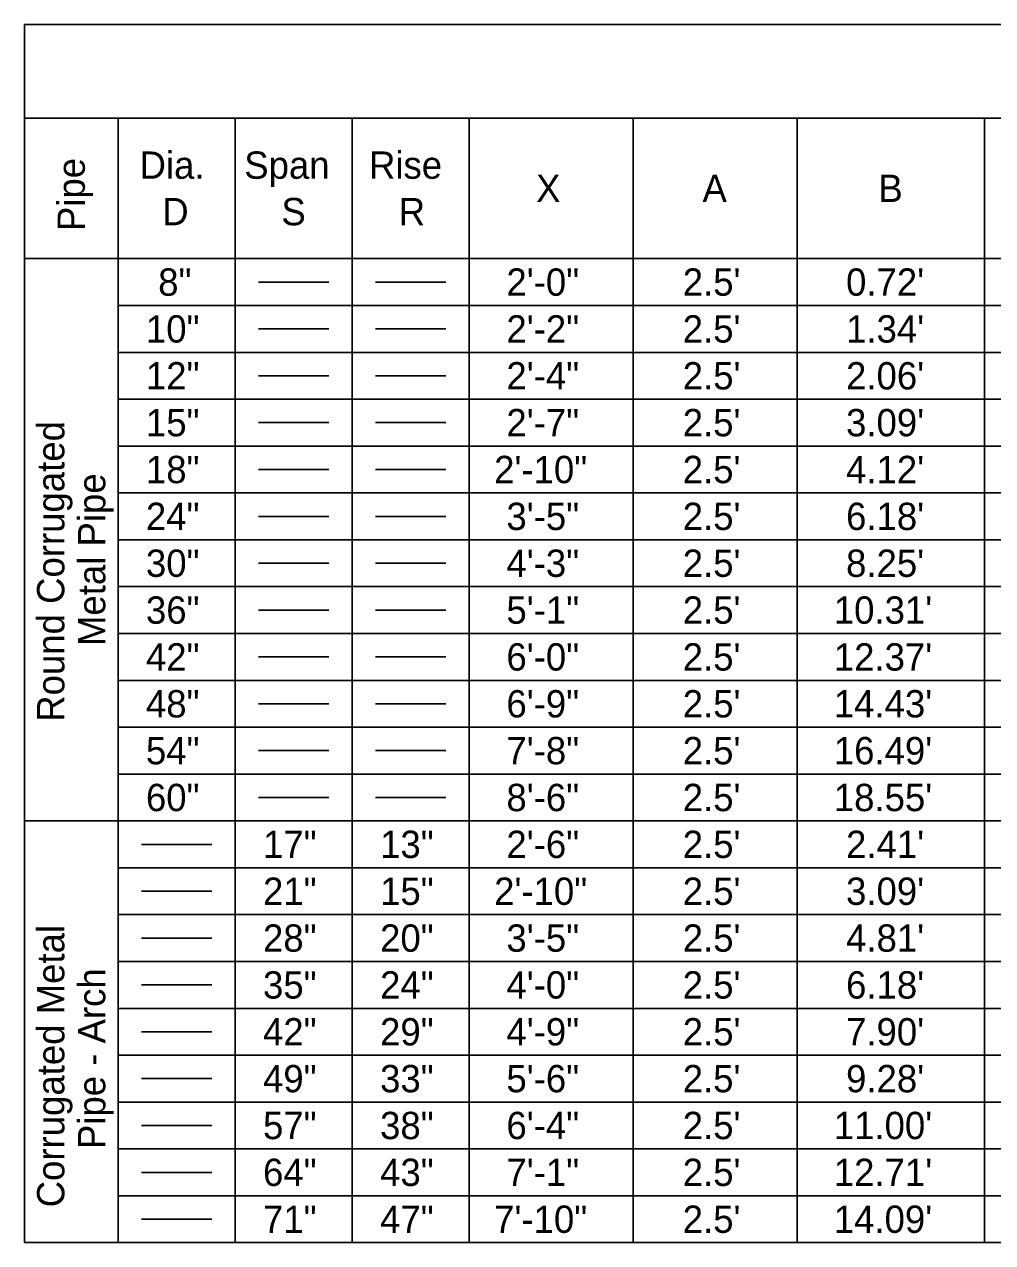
# Model space of a CAD drawing. Extents: x 2 to 14.4, y 0 to 6.5.
# Drawn here: x 2 to 4.481, y 3.39 to 6.51 of the extents above; entities that cross this region are included whole.
import ezdxf

# ---------------------------------------------------------------- set-up
doc = ezdxf.new("R2010")
doc.units = 0
doc.layers.add('TextNotes', color=7, linetype='Continuous')
doc.layers.add('TextTables', color=7, linetype='Continuous')

msp = doc.modelspace()

# ---------------------------------------------------------------- linework, layer by layer
at = {"layer": 'TextTables'}
for p, q in [((2, 6.51), (13.4, 6.51)), ((2.6, 5.85), (2.78, 5.85)), ((2.9, 5.85), (3.08, 5.85)), ((2.6, 5.73), (2.78, 5.73)), ((2.9, 5.73), (3.08, 5.73)), ((2.6, 5.61), (2.78, 5.61)), ((2.9, 5.61), (3.08, 5.61)), ((2.6, 5.49), (2.78, 5.49)), ((2.9, 5.49), (3.08, 5.49)), ((2.6, 5.37), (2.78, 5.37)), ((2.9, 5.37), (3.08, 5.37)), ((2.6, 5.25), (2.78, 5.25)), ((2.9, 5.25), (3.08, 5.25)), ((2.6, 5.13), (2.78, 5.13)), ((2.9, 5.13), (3.08, 5.13)), ((2.6, 5.01), (2.78, 5.01)), ((2.9, 5.01), (3.08, 5.01)), ((2.6, 4.89), (2.78, 4.89)), ((2.9, 4.89), (3.08, 4.89)), ((2.6, 4.77), (2.78, 4.77)), ((2.9, 4.77), (3.08, 4.77)), ((2.6, 4.65), (2.78, 4.65)), ((2.9, 4.65), (3.08, 4.65)), ((2.6, 4.53), (2.78, 4.53)), ((2.9, 4.53), (3.08, 4.53)), ((2.3, 4.41), (2.48, 4.41)), ((2.3, 4.29), (2.48, 4.29)), ((2.3, 4.17), (2.48, 4.17)), ((2.3, 4.05), (2.48, 4.05)), ((2.3, 3.93), (2.48, 3.93)), ((2.3, 3.81), (2.48, 3.81)), ((2.3, 3.69), (2.48, 3.69)), ((2.3, 3.57), (2.48, 3.57)), ((2.3, 3.45), (2.48, 3.45))]:
    msp.add_line(p, q, dxfattribs=at)
for points in [[(2, 6.51), (2, 6.27), (2, 5.91), (2, 4.47), (2, 3.39)], [(13.4, 6.27), (11.72, 6.27), (10.04, 6.27), (8.36, 6.27), (8, 6.27), (6.32, 6.27), (5.96, 6.27), (5.6, 6.27), (5.24, 6.27), (4.88, 6.27), (4.46, 6.27), (3.98, 6.27), (3.56, 6.27), (3.14, 6.27), (2.84, 6.27), (2.54, 6.27), (2.24, 6.27), (2, 6.27)], [(2.24, 6.27), (2.24, 5.91), (2.24, 5.79), (2.24, 5.67), (2.24, 5.55), (2.24, 5.43), (2.24, 5.31), (2.24, 5.19), (2.24, 5.07), (2.24, 4.95), (2.24, 4.83), (2.24, 4.71), (2.24, 4.59), (2.24, 4.47), (2.24, 4.35), (2.24, 4.23), (2.24, 4.11), (2.24, 3.99), (2.24, 3.87), (2.24, 3.75), (2.24, 3.63), (2.24, 3.51), (2.24, 3.39)], [(2.54, 6.27), (2.54, 5.91), (2.54, 5.79), (2.54, 5.67), (2.54, 5.55), (2.54, 5.43), (2.54, 5.31), (2.54, 5.19), (2.54, 5.07), (2.54, 4.95), (2.54, 4.83), (2.54, 4.71), (2.54, 4.59), (2.54, 4.47), (2.54, 4.35), (2.54, 4.23), (2.54, 4.11), (2.54, 3.99), (2.54, 3.87), (2.54, 3.75), (2.54, 3.63), (2.54, 3.51), (2.54, 3.39)], [(2.84, 6.27), (2.84, 5.91), (2.84, 5.79), (2.84, 5.67), (2.84, 5.55), (2.84, 5.43), (2.84, 5.31), (2.84, 5.19), (2.84, 5.07), (2.84, 4.95), (2.84, 4.83), (2.84, 4.71), (2.84, 4.59), (2.84, 4.47), (2.84, 4.35), (2.84, 4.23), (2.84, 4.11), (2.84, 3.99), (2.84, 3.87), (2.84, 3.75), (2.84, 3.63), (2.84, 3.51), (2.84, 3.39)], [(3.14, 6.27), (3.14, 5.91), (3.14, 5.79), (3.14, 5.67), (3.14, 5.55), (3.14, 5.43), (3.14, 5.31), (3.14, 5.19), (3.14, 5.07), (3.14, 4.95), (3.14, 4.83), (3.14, 4.71), (3.14, 4.59), (3.14, 4.47), (3.14, 4.35), (3.14, 4.23), (3.14, 4.11), (3.14, 3.99), (3.14, 3.87), (3.14, 3.75), (3.14, 3.63), (3.14, 3.51), (3.14, 3.39)], [(3.56, 6.27), (3.56, 5.91), (3.56, 5.79), (3.56, 5.67), (3.56, 5.55), (3.56, 5.43), (3.56, 5.31), (3.56, 5.19), (3.56, 5.07), (3.56, 4.95), (3.56, 4.83), (3.56, 4.71), (3.56, 4.59), (3.56, 4.47), (3.56, 4.35), (3.56, 4.23), (3.56, 4.11), (3.56, 3.99), (3.56, 3.87), (3.56, 3.75), (3.56, 3.63), (3.56, 3.51), (3.56, 3.39)], [(3.98, 6.27), (3.98, 5.91), (3.98, 5.79), (3.98, 5.67), (3.98, 5.55), (3.98, 5.43), (3.98, 5.31), (3.98, 5.19), (3.98, 5.07), (3.98, 4.95), (3.98, 4.83), (3.98, 4.71), (3.98, 4.59), (3.98, 4.47), (3.98, 4.35), (3.98, 4.23), (3.98, 4.11), (3.98, 3.99), (3.98, 3.87), (3.98, 3.75), (3.98, 3.63), (3.98, 3.51), (3.98, 3.39)], [(4.46, 6.27), (4.46, 5.91), (4.46, 5.79), (4.46, 5.67), (4.46, 5.55), (4.46, 5.43), (4.46, 5.31), (4.46, 5.19), (4.46, 5.07), (4.46, 4.95), (4.46, 4.83), (4.46, 4.71), (4.46, 4.59), (4.46, 4.47), (4.46, 4.35), (4.46, 4.23), (4.46, 4.11), (4.46, 3.99), (4.46, 3.87), (4.46, 3.75), (4.46, 3.63), (4.46, 3.51), (4.46, 3.39)], [(2, 5.91), (2.24, 5.91), (2.54, 5.91), (2.84, 5.91), (3.14, 5.91), (3.56, 5.91), (3.98, 5.91), (4.46, 5.91), (4.88, 5.91), (5.24, 5.91), (5.6, 5.91), (5.96, 5.91), (6.32, 5.91), (6.74, 5.91), (7.16, 5.91), (7.58, 5.91), (8, 5.91), (8.36, 5.91)], [(2.24, 5.79), (2.54, 5.79), (2.84, 5.79), (3.14, 5.79), (3.56, 5.79), (3.98, 5.79), (4.46, 5.79), (4.88, 5.79), (5.24, 5.79), (5.6, 5.79), (5.96, 5.79), (6.32, 5.79), (6.74, 5.79), (7.16, 5.79), (7.58, 5.79), (8, 5.79), (8.36, 5.79)], [(2.24, 5.67), (2.54, 5.67), (2.84, 5.67), (3.14, 5.67), (3.56, 5.67), (3.98, 5.67), (4.46, 5.67), (4.88, 5.67), (5.24, 5.67), (5.6, 5.67), (5.96, 5.67), (6.32, 5.67), (6.74, 5.67), (7.16, 5.67), (7.58, 5.67), (8, 5.67), (8.36, 5.67)], [(2.24, 5.55), (2.54, 5.55), (2.84, 5.55), (3.14, 5.55), (3.56, 5.55), (3.98, 5.55), (4.46, 5.55), (4.88, 5.55), (5.24, 5.55), (5.6, 5.55), (5.96, 5.55), (6.32, 5.55), (6.74, 5.55), (7.16, 5.55), (7.58, 5.55), (8, 5.55), (8.36, 5.55)], [(2.24, 5.43), (2.54, 5.43), (2.84, 5.43), (3.14, 5.43), (3.56, 5.43), (3.98, 5.43), (4.46, 5.43), (4.88, 5.43), (5.24, 5.43), (5.6, 5.43), (5.96, 5.43), (6.32, 5.43), (6.74, 5.43), (7.16, 5.43), (7.58, 5.43), (8, 5.43), (8.36, 5.43)], [(2.24, 5.31), (2.54, 5.31), (2.84, 5.31), (3.14, 5.31), (3.56, 5.31), (3.98, 5.31), (4.46, 5.31), (4.88, 5.31), (5.24, 5.31), (5.6, 5.31), (5.96, 5.31), (6.32, 5.31), (6.74, 5.31), (7.16, 5.31), (7.58, 5.31), (8, 5.31), (8.36, 5.31)], [(2.24, 5.19), (2.54, 5.19), (2.84, 5.19), (3.14, 5.19), (3.56, 5.19), (3.98, 5.19), (4.46, 5.19), (4.88, 5.19), (5.24, 5.19), (5.6, 5.19), (5.96, 5.19), (6.32, 5.19), (6.74, 5.19), (7.16, 5.19), (7.58, 5.19), (8, 5.19), (8.36, 5.19)], [(2.24, 5.07), (2.54, 5.07), (2.84, 5.07), (3.14, 5.07), (3.56, 5.07), (3.98, 5.07), (4.46, 5.07), (4.88, 5.07), (5.24, 5.07), (5.6, 5.07), (5.96, 5.07), (6.32, 5.07), (6.74, 5.07), (7.16, 5.07), (7.58, 5.07), (8, 5.07), (8.36, 5.07)], [(2.24, 4.95), (2.54, 4.95), (2.84, 4.95), (3.14, 4.95), (3.56, 4.95), (3.98, 4.95), (4.46, 4.95), (4.88, 4.95), (5.24, 4.95), (5.6, 4.95), (5.96, 4.95), (6.32, 4.95), (6.74, 4.95), (7.16, 4.95), (7.58, 4.95), (8, 4.95), (8.36, 4.95)], [(2.24, 4.83), (2.54, 4.83), (2.84, 4.83), (3.14, 4.83), (3.56, 4.83), (3.98, 4.83), (4.46, 4.83), (4.88, 4.83), (5.24, 4.83), (5.6, 4.83), (5.96, 4.83), (6.32, 4.83), (6.74, 4.83), (7.16, 4.83), (7.58, 4.83), (8, 4.83), (8.36, 4.83)], [(2.24, 4.71), (2.54, 4.71), (2.84, 4.71), (3.14, 4.71), (3.56, 4.71), (3.98, 4.71), (4.46, 4.71), (4.88, 4.71), (5.24, 4.71), (5.6, 4.71), (5.96, 4.71), (6.32, 4.71), (6.74, 4.71), (7.16, 4.71), (7.58, 4.71), (8, 4.71), (8.36, 4.71)], [(2.24, 4.59), (2.54, 4.59), (2.84, 4.59), (3.14, 4.59), (3.56, 4.59), (3.98, 4.59), (4.46, 4.59), (4.88, 4.59), (5.24, 4.59), (5.6, 4.59), (5.96, 4.59), (6.32, 4.59), (6.74, 4.59), (7.16, 4.59), (7.58, 4.59), (8, 4.59), (8.36, 4.59)], [(2, 4.47), (2.24, 4.47), (2.54, 4.47), (2.84, 4.47), (3.14, 4.47), (3.56, 4.47), (3.98, 4.47), (4.46, 4.47), (4.88, 4.47), (5.24, 4.47), (5.6, 4.47), (5.96, 4.47), (6.32, 4.47), (6.74, 4.47), (7.16, 4.47), (7.58, 4.47), (8, 4.47), (8.36, 4.47)], [(2.24, 4.47), (2.54, 4.47), (2.84, 4.47), (3.14, 4.47), (3.56, 4.47), (3.98, 4.47), (4.46, 4.47), (4.88, 4.47), (5.24, 4.47), (5.6, 4.47), (5.96, 4.47), (6.32, 4.47), (6.74, 4.47), (7.16, 4.47), (7.58, 4.47), (8, 4.47), (8.36, 4.47)], [(2.24, 4.35), (2.54, 4.35), (2.84, 4.35), (3.14, 4.35), (3.56, 4.35), (3.98, 4.35), (4.46, 4.35), (4.88, 4.35), (5.24, 4.35), (5.6, 4.35), (5.96, 4.35), (6.32, 4.35), (6.74, 4.35), (7.16, 4.35), (7.58, 4.35), (8, 4.35), (8.36, 4.35)], [(2.24, 4.23), (2.54, 4.23), (2.84, 4.23), (3.14, 4.23), (3.56, 4.23), (3.98, 4.23), (4.46, 4.23), (4.88, 4.23), (5.24, 4.23), (5.6, 4.23), (5.96, 4.23), (6.32, 4.23), (6.74, 4.23), (7.16, 4.23), (7.58, 4.23), (8, 4.23), (8.36, 4.23)], [(2.24, 4.11), (2.54, 4.11), (2.84, 4.11), (3.14, 4.11), (3.56, 4.11), (3.98, 4.11), (4.46, 4.11), (4.88, 4.11), (5.24, 4.11), (5.6, 4.11), (5.96, 4.11), (6.32, 4.11), (6.74, 4.11), (7.16, 4.11), (7.58, 4.11), (8, 4.11), (8.36, 4.11)], [(2.24, 3.99), (2.54, 3.99), (2.84, 3.99), (3.14, 3.99), (3.56, 3.99), (3.98, 3.99), (4.46, 3.99), (4.88, 3.99), (5.24, 3.99), (5.6, 3.99), (5.96, 3.99), (6.32, 3.99), (6.74, 3.99), (7.16, 3.99), (7.58, 3.99), (8, 3.99), (8.36, 3.99)], [(2.24, 3.87), (2.54, 3.87), (2.84, 3.87), (3.14, 3.87), (3.56, 3.87), (3.98, 3.87), (4.46, 3.87), (4.88, 3.87), (5.24, 3.87), (5.6, 3.87), (5.96, 3.87), (6.32, 3.87), (6.74, 3.87), (7.16, 3.87), (7.58, 3.87), (8, 3.87), (8.36, 3.87)], [(2.24, 3.75), (2.54, 3.75), (2.84, 3.75), (3.14, 3.75), (3.56, 3.75), (3.98, 3.75), (4.46, 3.75), (4.88, 3.75), (5.24, 3.75), (5.6, 3.75), (5.96, 3.75), (6.32, 3.75), (6.74, 3.75), (7.16, 3.75), (7.58, 3.75), (8, 3.75), (8.36, 3.75)], [(2.24, 3.63), (2.54, 3.63), (2.84, 3.63), (3.14, 3.63), (3.56, 3.63), (3.98, 3.63), (4.46, 3.63), (4.88, 3.63), (5.24, 3.63), (5.6, 3.63), (5.96, 3.63), (6.32, 3.63), (6.74, 3.63), (7.16, 3.63), (7.58, 3.63), (8, 3.63), (8.36, 3.63)], [(2.24, 3.51), (2.54, 3.51), (2.84, 3.51), (3.14, 3.51), (3.56, 3.51), (3.98, 3.51), (4.46, 3.51), (4.88, 3.51), (5.24, 3.51), (5.6, 3.51), (5.96, 3.51), (6.32, 3.51), (6.74, 3.51), (7.16, 3.51), (7.58, 3.51), (8, 3.51), (8.36, 3.51)], [(2, 3.39), (2.24, 3.39), (2.54, 3.39), (2.84, 3.39), (3.14, 3.39), (3.56, 3.39), (3.98, 3.39), (4.46, 3.39), (4.88, 3.39), (5.24, 3.39), (5.6, 3.39), (5.96, 3.39), (6.32, 3.39), (6.74, 3.39), (7.16, 3.39), (7.58, 3.39), (8, 3.39), (8.36, 3.39)]]:
    msp.add_lwpolyline(points, dxfattribs=at)

# ---------------------------------------------------------------- texts
at = {"layer": 'TextNotes'}
for s, p in [('Dia.', (2.2952, 6.1145)), ('Span', (2.5634, 6.1145)), ('Rise', (2.8831, 6.1145)), ('X', (3.3112, 6.055)), ('A', (3.7375, 6.055)), ('B', (4.1883, 6.055)), ('D', (2.3534, 5.9955)), ('S', (2.6586, 5.9955)), ('R', (2.9592, 5.9955))]:
    msp.add_text(s, height=0.07, dxfattribs=at).set_placement(p)
for s, rotation, p in [('Pipe', 90, (2.155, 5.9806)), ('8"', 0, (2.3429, 5.815)), ('2\'-0"', 0, (3.2351, 5.815)), ("2.5'", 0, (3.6869, 5.815)), ("0.72'", 0, (4.1054, 5.815)), ('10"', 0, (2.3115, 5.695)), ('2\'-2"', 0, (3.2351, 5.695)), ("2.5'", 0, (3.6869, 5.695)), ("1.34'", 0, (4.1054, 5.695)), ('12"', 0, (2.3115, 5.575)), ('2\'-4"', 0, (3.2351, 5.575)), ("2.5'", 0, (3.6869, 5.575)), ("2.06'", 0, (4.1054, 5.575)), ('15"', 0, (2.3115, 5.455)), ('2\'-7"', 0, (3.2351, 5.455)), ("2.5'", 0, (3.6869, 5.455)), ("3.09'", 0, (4.1054, 5.455)), ('Round Corrugated', 90, (2.1025, 4.7239)), ('18"', 0, (2.3115, 5.335)), ('2\'-10"', 0, (3.2037, 5.335)), ("2.5'", 0, (3.6869, 5.335)), ("4.12'", 0, (4.1054, 5.335)), ('Metal Pipe', 90, (2.2075, 4.9179)), ('24"', 0, (2.3115, 5.215)), ('3\'-5"', 0, (3.2351, 5.215)), ("2.5'", 0, (3.6869, 5.215)), ("6.18'", 0, (4.1054, 5.215)), ('30"', 0, (2.3115, 5.095)), ('4\'-3"', 0, (3.2351, 5.095)), ("2.5'", 0, (3.6869, 5.095)), ("8.25'", 0, (4.1054, 5.095)), ('36"', 0, (2.3115, 4.975)), ('5\'-1"', 0, (3.2351, 4.975)), ("2.5'", 0, (3.6869, 4.975)), ("10.31'", 0, (4.074, 4.975)), ('42"', 0, (2.3115, 4.855)), ('6\'-0"', 0, (3.2351, 4.855)), ("2.5'", 0, (3.6869, 4.855)), ("12.37'", 0, (4.074, 4.855)), ('48"', 0, (2.3115, 4.735)), ('6\'-9"', 0, (3.2351, 4.735)), ("2.5'", 0, (3.6869, 4.735)), ("14.43'", 0, (4.074, 4.735)), ('54"', 0, (2.3115, 4.615)), ('7\'-8"', 0, (3.2351, 4.615)), ("2.5'", 0, (3.6869, 4.615)), ("16.49'", 0, (4.074, 4.615)), ('60"', 0, (2.3115, 4.495)), ('8\'-6"', 0, (3.2351, 4.495)), ("2.5'", 0, (3.6869, 4.495)), ("18.55'", 0, (4.074, 4.495)), ('17"', 0, (2.6115, 4.375)), ('13"', 0, (2.9115, 4.375)), ('2\'-6"', 0, (3.2351, 4.375)), ("2.5'", 0, (3.6869, 4.375)), ("2.41'", 0, (4.1054, 4.375)), ('21"', 0, (2.6115, 4.255)), ('15"', 0, (2.9115, 4.255)), ('2\'-10"', 0, (3.2037, 4.255)), ("2.5'", 0, (3.6869, 4.255)), ("3.09'", 0, (4.1054, 4.255)), ('Corrugated Metal ', 90, (2.1025, 3.4804)), ('28"', 0, (2.6115, 4.135)), ('20"', 0, (2.9115, 4.135)), ('3\'-5"', 0, (3.2351, 4.135)), ("2.5'", 0, (3.6869, 4.135)), ("4.81'", 0, (4.1054, 4.135)), ('Pipe - Arch', 90, (2.2075, 3.6296)), ('35"', 0, (2.6115, 4.015)), ('24"', 0, (2.9115, 4.015)), ('4\'-0"', 0, (3.2351, 4.015)), ("2.5'", 0, (3.6869, 4.015)), ("6.18'", 0, (4.1054, 4.015)), ('42"', 0, (2.6115, 3.895)), ('29"', 0, (2.9115, 3.895)), ('4\'-9"', 0, (3.2351, 3.895)), ("2.5'", 0, (3.6869, 3.895)), ("7.90'", 0, (4.1054, 3.895)), ('49"', 0, (2.6115, 3.775)), ('33"', 0, (2.9115, 3.775)), ('5\'-6"', 0, (3.2351, 3.775)), ("2.5'", 0, (3.6869, 3.775)), ("9.28'", 0, (4.1054, 3.775)), ('57"', 0, (2.6115, 3.655)), ('38"', 0, (2.9115, 3.655)), ('6\'-4"', 0, (3.2351, 3.655)), ("2.5'", 0, (3.6869, 3.655)), ("11.00'", 0, (4.074, 3.655)), ('64"', 0, (2.6115, 3.535)), ('43"', 0, (2.9115, 3.535)), ('7\'-1"', 0, (3.2351, 3.535)), ("2.5'", 0, (3.6869, 3.535)), ("12.71'", 0, (4.074, 3.535)), ('71"', 0, (2.6115, 3.415)), ('47"', 0, (2.9115, 3.415)), ('7\'-10"', 0, (3.2037, 3.415)), ("2.5'", 0, (3.6869, 3.415)), ("14.09'", 0, (4.074, 3.415))]:
    msp.add_text(s, height=0.07, rotation=rotation, dxfattribs=at).set_placement(p)

doc.saveas('drawing.dxf')
